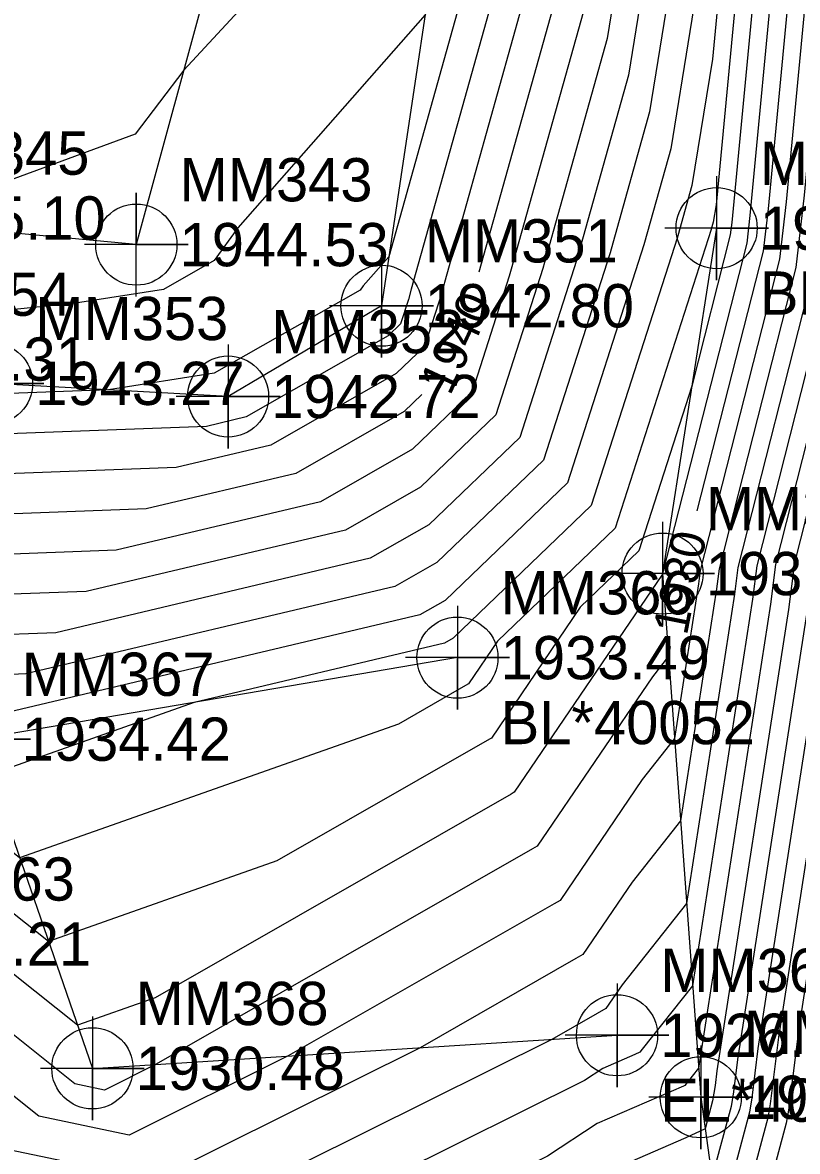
# Model space of a CAD drawing. Extents: x 1004378 to 1005103, y 553854 to 554288.
# Drawn here: x 1004921.7 to 1004966.5, y 553915.8 to 553981 of the extents above; entities that cross this region are included whole.
import ezdxf

# ---------------------------------------------------------------- set-up
doc = ezdxf.new("R2010")
doc.units = 0
for name, color, linetype in [('DTM Contours Major', 7, 'Continuous'), ('DTM Contours Major Text', 7, 'Continuous'), ('DTM Contours Minor', 7, 'Continuous'), ('Exist DTM Breakline', 7, 'Continuous'), ('Exist DTM Breakline Cogo Comment', 7, 'Continuous'), ('Exist DTM Breakline Cogo Elevation', 7, 'Continuous'), ('Exist DTM Breakline Cogo Number', 7, 'Continuous'), ('Exist DTM Breakline Cogo Point CELL', 7, 'Continuous'), ('Exist Roads Soil', 7, 'Continuous'), ('Exist Roads Soil Cogo Elevation', 7, 'Continuous'), ('Exist Roads Soil Cogo Number', 7, 'Continuous'), ('Exist Roads Soil Cogo Point CELL', 7, 'Continuous')]:
    doc.layers.add(name, color=color, linetype=linetype)

msp = doc.modelspace()

# ---------------------------------------------------------------- linework, layer by layer
at = {"layer": 'DTM Contours Major'}
for points in [[(1004952.659, 554065.091), (1004953.349, 554059.3), (1004954.06, 554055.889), (1004955.156, 554052.277), (1004953.842, 554048.264), (1004954.035, 554026.446), (1004955.827, 554009.057), (1004955.839, 554007.597), (1004955.608, 554000.346), (1004953.019, 553984.313), (1004948.054, 553966.564)], [(1004966.938, 554051.86), (1004967.829, 554048.921), (1004967.422, 554047.677), (1004967.482, 554040.91), (1004968.579, 554030.261), (1004968.073, 554007.661), (1004967.778, 554001.521), (1004967.551, 553999.619), (1004964.757, 553970.225), (1004964.471, 553967.778), (1004960.654, 553952.767)], [(1004947.118, 554041.088), (1004947.311, 554019.215), (1004947.454, 554017.827), (1004947.487, 554013.967), (1004946.931, 553996.538), (1004946.571, 553995.053), (1004931.009, 553978.241), (1004928.196, 553974.545), (1004916.189, 553970.124), (1004914.888, 553969.412), (1004912.358, 553969.149), (1004911.765, 553968.617), (1004911.067, 553969.318), (1004903.448, 553970.699)], [(1004962.31, 553997.555), (1004961.333, 553987.27), (1004959.141, 553973.696), (1004957.624, 553968.273), (1004957.585, 553968.134), (1004953.163, 553954.39), (1004946.098, 553947.597), (1004944.639, 553946.764), (1004920.141, 553940.962), (1004919.187, 553940.926), (1004918.652, 553940.867), (1004916.351, 553941.407), (1004903.524, 553943.188), (1004903.229, 553940.965)], [(1004971.479, 553987.875), (1004969.989, 553972.194), (1004969.198, 553965.438), (1004965.192, 553949.68), (1004964.904, 553947.376), (1004960.748, 553920.578), (1004960.368, 553920.099), (1004959.949, 553919.572), (1004959.874, 553919.536), (1004954.889, 553917.367), (1004952.025, 553915.484), (1004933.597, 553906.315), (1004932.685, 553906.503)], [(1004975.8, 553980.258), (1004975.22, 553974.163), (1004973.925, 553963.098), (1004970.627, 553950.123), (1004970.099, 553945.901), (1004966.549, 553923.013), (1004965.932, 553918.15), (1004965.808, 553917.384), (1004962.695, 553905.72), (1004954.669, 553902.046), (1004953.262, 553901.433), (1004941.713, 553893.841)], [(1004944.754, 553959.487), (1004943.743, 553958.515), (1004937.467, 553954.931), (1004928.829, 553952.886), (1004919.63, 553952.541), (1004914.473, 553951.967), (1004901.641, 553954.979), (1004896.468, 553952.368), (1004896.162, 553950.066), (1004894.709, 553945.812), (1004892.507, 553943.392)], [(1004959.1, 553944.929), (1004959.013, 553944.368), (1004958.077, 553943.19), (1004951.417, 553933.392), (1004951.155, 553933.242), (1004929.405, 553920.793), (1004926.414, 553919.305), (1004924.709, 553919.658), (1004920.162, 553923.286), (1004912.286, 553929.547), (1004910.029, 553929.86), (1004909.966, 553929.387), (1004909.292, 553927.413), (1004906.06, 553916.388), (1004903.403, 553900.976), (1004901.694, 553893.379)]]:
    msp.add_lwpolyline(points, dxfattribs=at)
at = {"layer": 'DTM Contours Minor'}
for points in [[(1004948.41, 554048.498), (1004948.656, 554020.661), (1004949.129, 554016.073), (1004949.157, 554012.693), (1004948.622, 553995.909), (1004948.121, 553992.807), (1004944.939, 553981.431), (1004934.117, 553969.131), (1004932.752, 553967.238), (1004929.819, 553965.57), (1004924.739, 553964.771), (1004916.73, 553963.94), (1004913.587, 553961.121), (1004911.131, 553960.847), (1004910.199, 553961.066), (1004909.391, 553960.658), (1004907.185, 553961.606), (1004903.082, 553965.731), (1004892.29, 553967.686), (1004891.326, 553967.931), (1004890.511, 553967.035)], [(1004949.768, 554048.44), (1004950.001, 554022.107), (1004950.803, 554014.319), (1004950.827, 554011.419), (1004950.368, 553997.019), (1004949.345, 553990.683), (1004942.849, 553967.456), (1004941.373, 553965.778), (1004941.187, 553965.52), (1004932.749, 553960.721), (1004926.659, 553959.763), (1004919.896, 553959.51), (1004911.966, 553958.627), (1004908.059, 553959.544), (1004904.674, 553957.836), (1004895.429, 553961.81), (1004895.097, 553962.143), (1004894.225, 553962.301), (1004892.484, 553962.744), (1004891.01, 553961.125)], [(1004951.126, 554048.381), (1004951.345, 554023.554), (1004952.478, 554012.565), (1004952.498, 554010.145), (1004952.115, 553998.128), (1004950.57, 553988.56), (1004944.141, 553965.574), (1004943.976, 553964.983), (1004943.524, 553963.577), (1004942.801, 553962.882), (1004934.598, 553958.198), (1004932.304, 553957.655), (1004919.808, 553957.187), (1004912.802, 553956.407), (1004905.92, 553958.023), (1004899.957, 553955.013), (1004894.62, 553957.307), (1004893.641, 553957.556), (1004891.509, 553955.214)], [(1004952.484, 554048.322), (1004952.69, 554025), (1004954.152, 554010.811), (1004954.168, 554008.871), (1004953.861, 553999.237), (1004951.794, 553986.437), (1004946.067, 553965.959), (1004945.92, 553965.433), (1004944.901, 553962.265), (1004943.272, 553960.699), (1004936.032, 553956.565), (1004930.566, 553955.27), (1004919.719, 553954.864), (1004913.638, 553954.187), (1004903.78, 553956.501), (1004895.24, 553952.191), (1004894.867, 553952.351), (1004894.798, 553952.369), (1004892.008, 553949.303)], [(1004955.2, 554048.205), (1004955.379, 554027.893), (1004957.501, 554007.303), (1004957.509, 554006.323), (1004957.354, 554001.455), (1004954.243, 553982.19), (1004949.919, 553966.731), (1004949.808, 553966.333), (1004947.655, 553959.64), (1004944.214, 553956.331), (1004938.901, 553953.298), (1004927.091, 553950.501), (1004919.542, 553950.218), (1004915.309, 553949.747), (1004899.502, 553953.458), (1004898.18, 553952.79), (1004897.542, 553947.998), (1004894.519, 553939.143), (1004893.007, 553937.482)], [(1004956.558, 554048.146), (1004956.724, 554029.339), (1004959.176, 554005.549), (1004959.18, 554005.049), (1004959.101, 554002.565), (1004955.467, 553980.066), (1004951.846, 553967.116), (1004951.753, 553966.783), (1004949.032, 553958.328), (1004944.685, 553954.148), (1004940.335, 553951.664), (1004925.354, 553948.116), (1004919.453, 553947.895), (1004916.145, 553947.527), (1004901.925, 553950.865), (1004899.622, 553951.185), (1004898.923, 553945.93), (1004894.328, 553932.475), (1004893.506, 553931.571)], [(1004957.916, 554048.088), (1004958.069, 554030.785), (1004960.85, 554003.795), (1004960.85, 554003.775), (1004960.847, 554003.674), (1004956.692, 553977.943), (1004953.772, 553967.502), (1004953.697, 553967.233), (1004950.409, 553957.015), (1004945.156, 553951.964), (1004941.77, 553950.031), (1004923.616, 553945.732), (1004919.364, 553945.572), (1004916.98, 553945.307), (1004906.734, 553947.712), (1004900.923, 553948.519), (1004900.303, 553943.862), (1004894.138, 553925.806), (1004894.005, 553925.66)], [(1004972.981, 554045.52), (1004972.185, 554009.926), (1004971.721, 554000.256), (1004971.362, 553997.261), (1004968.942, 553971.8), (1004968.253, 553965.906), (1004964.105, 553949.591), (1004963.865, 553947.671), (1004960.401, 553925.336), (1004957.491, 553921.673), (1004957.35, 553921.495), (1004957.063, 553921.358), (1004955.215, 553920.554), (1004954.153, 553919.855), (1004932.16, 553908.913), (1004916.353, 553912.182), (1004913.842, 553914.186), (1004913.087, 553911.609), (1004912.621, 553908.909), (1004907.637, 553886.746), (1004907.279, 553884.335), (1004906.612, 553883.292), (1004908.282, 553879.28)], [(1004975.015, 554045.638), (1004974.241, 554011.059), (1004973.692, 553999.624), (1004973.268, 553996.082), (1004971.035, 553972.588), (1004970.143, 553964.97), (1004966.279, 553949.768), (1004965.943, 553947.081), (1004961.807, 553920.414), (1004961.699, 553919.562), (1004961.557, 553918.68), (1004961.124, 553917.06), (1004960.01, 553916.55), (1004954.564, 553914.18), (1004949.897, 553911.112), (1004935.034, 553903.717), (1004920.298, 553906.764), (1004913.738, 553897.346), (1004910.842, 553884.469), (1004910.705, 553883.545), (1004910.449, 553883.146), (1004912.725, 553877.68)], [(1004976.003, 554044.458), (1004975.269, 554011.625), (1004974.678, 553999.308), (1004974.221, 553995.492), (1004972.081, 553972.981), (1004971.089, 553964.502), (1004967.366, 553949.857), (1004966.982, 553946.786), (1004962.993, 553921.064), (1004962.757, 553919.209), (1004962.62, 553918.356), (1004961.517, 553914.225), (1004958.675, 553912.924), (1004954.239, 553910.994), (1004947.768, 553906.74), (1004936.47, 553901.118), (1004925.269, 553903.435), (1004913.007, 553885.833), (1004912.444, 553883.33), (1004912.418, 553883.151), (1004912.368, 553883.073), (1004914.946, 553876.88)], [(1004976.992, 554043.278), (1004976.297, 554012.192), (1004975.663, 553998.992), (1004975.174, 553994.903), (1004973.128, 553973.375), (1004972.034, 553964.034), (1004968.453, 553949.946), (1004968.021, 553946.491), (1004964.178, 553921.714), (1004963.816, 553918.856), (1004963.683, 553918.032), (1004961.91, 553911.39), (1004957.339, 553909.298), (1004953.913, 553907.807), (1004945.64, 553902.368), (1004937.907, 553898.52), (1004930.24, 553900.106), (1004920.136, 553885.602), (1004914.696, 553882.016), (1004917.167, 553876.081)], [(1004977.981, 554042.098), (1004977.325, 554012.758), (1004976.649, 553998.676), (1004976.126, 553994.313), (1004974.174, 553973.769), (1004972.98, 553963.566), (1004969.54, 553950.035), (1004969.06, 553946.196), (1004965.364, 553922.363), (1004964.874, 553918.503), (1004964.745, 553917.708), (1004962.303, 553908.555), (1004956.004, 553905.672), (1004953.588, 553904.62), (1004943.512, 553897.997), (1004939.343, 553895.922), (1004935.21, 553896.777), (1004929.764, 553888.959), (1004917.155, 553880.646), (1004919.388, 553875.281)], [(1004971.881, 554041.705), (1004971.157, 554009.36), (1004970.735, 554000.573), (1004970.409, 553997.85), (1004967.896, 553971.406), (1004967.307, 553966.374), (1004963.018, 553949.502), (1004962.826, 553947.966), (1004960.054, 553930.094), (1004956.322, 553925.395), (1004955.382, 553924.012), (1004954.895, 553923.733), (1004952.275, 553922.234), (1004930.724, 553911.511), (1004918.442, 553914.051), (1004912.975, 553918.414), (1004911.33, 553912.804), (1004910.317, 553906.926), (1004906.034, 553887.884), (1004905.566, 553884.73), (1004904.694, 553883.365), (1004906.061, 553880.08)], [(1004966.137, 554039.463), (1004967.478, 554026.447), (1004967.045, 554007.095), (1004966.793, 554001.837), (1004966.598, 554000.209), (1004963.711, 553969.831), (1004963.525, 553968.246), (1004958.67, 553949.147), (1004958.67, 553949.145), (1004958.667, 553949.126), (1004958.663, 553949.121), (1004950.096, 553936.518), (1004949.909, 553936.411), (1004929.348, 553924.643), (1004924.856, 553923.056), (1004913.836, 553931.817), (1004908.728, 553932.526), (1004908.586, 553931.455), (1004907.061, 553926.988), (1004904.303, 553917.582), (1004901.098, 553898.992)], [(1004964.792, 554038.017), (1004966.378, 554022.632), (1004966.017, 554006.528), (1004965.807, 554002.153), (1004965.645, 554000.798), (1004962.665, 553969.437), (1004962.58, 553968.714), (1004960.36, 553959.981), (1004957.294, 553950.453), (1004953.909, 553947.198), (1004948.774, 553939.645), (1004948.663, 553939.581), (1004936.373, 553932.547), (1004923.184, 553927.887), (1004915.385, 553934.086), (1004907.427, 553935.191), (1004907.205, 553933.523), (1004904.829, 553926.563), (1004902.546, 553918.777), (1004898.793, 553897.009)], [(1004970.78, 554037.89), (1004970.129, 554008.794), (1004969.75, 554000.889), (1004969.456, 553998.44), (1004966.85, 553971.012), (1004966.362, 553966.842), (1004961.931, 553949.413), (1004961.787, 553948.261), (1004959.707, 553934.852), (1004956.907, 553931.326), (1004954.06, 553927.139), (1004953.648, 553926.903), (1004944.652, 553921.754), (1004929.287, 553914.109), (1004920.531, 553915.92), (1004912.107, 553922.642), (1004909.573, 553913.998), (1004908.012, 553904.943), (1004904.431, 553889.023), (1004903.852, 553885.125), (1004902.775, 553883.437), (1004903.84, 553880.88)], [(1004963.448, 554036.571), (1004965.277, 554018.817), (1004964.989, 554005.962), (1004964.822, 554002.47), (1004964.692, 554001.388), (1004961.753, 553970.463), (1004961.589, 553969.449), (1004961.476, 553969.044), (1004961.473, 553969.034), (1004955.917, 553951.766), (1004949.132, 553945.241), (1004947.453, 553942.771), (1004947.416, 553942.75), (1004943.398, 553940.451), (1004921.511, 553932.717), (1004916.934, 553936.356), (1004906.126, 553937.857), (1004905.825, 553935.591), (1004902.597, 553926.138), (1004900.789, 553919.972), (1004896.488, 553895.026)], [(1004962.103, 554035.124), (1004964.176, 554015.003), (1004963.961, 554005.396), (1004963.836, 554002.786), (1004963.739, 554001.977), (1004961.543, 553978.867), (1004960.365, 553971.573), (1004959.55, 553968.659), (1004959.529, 553968.584), (1004954.54, 553953.078), (1004946.569, 553945.413), (1004946.073, 553945.13), (1004931.594, 553941.701), (1004919.839, 553937.548), (1004918.483, 553938.626), (1004904.825, 553940.523), (1004904.444, 553937.659), (1004900.366, 553925.713), (1004899.032, 553921.166), (1004895.735, 553902.041), (1004895.123, 553902.853)], [(1004969.679, 554034.076), (1004969.101, 554008.227), (1004968.764, 554001.205), (1004968.504, 553999.029), (1004965.804, 553970.618), (1004965.416, 553967.31), (1004960.844, 553949.324), (1004960.748, 553948.556), (1004959.36, 553939.61), (1004957.492, 553937.258), (1004952.739, 553930.265), (1004952.402, 553930.072), (1004937.029, 553921.274), (1004927.851, 553916.707), (1004922.62, 553917.789), (1004911.24, 553926.87), (1004907.816, 553915.193), (1004905.707, 553902.959), (1004902.829, 553890.161), (1004902.139, 553885.52), (1004900.857, 553883.51), (1004901.619, 553881.68)], [(1004959.413, 554032.232), (1004961.975, 554007.374), (1004961.905, 554004.263), (1004961.865, 554003.418), (1004961.833, 554003.156), (1004961.122, 553995.674), (1004957.916, 553975.82), (1004955.698, 553967.888), (1004955.641, 553967.684), (1004951.786, 553955.703), (1004945.627, 553949.78), (1004943.204, 553948.397), (1004921.879, 553943.347), (1004919.275, 553943.249), (1004917.816, 553943.087), (1004911.542, 553944.56), (1004902.224, 553945.854), (1004901.684, 553941.794), (1004895.902, 553924.863), (1004895.519, 553923.556), (1004894.571, 553918.057), (1004894.395, 553918.29)]]:
    msp.add_lwpolyline(points, dxfattribs=at)
at = {"layer": 'Exist DTM Breakline'}
for points in [[(1004908.599, 554113.626), (1004928.542, 554104.358), (1004950.697, 554094.299), (1004945.541, 554080.331), (1004948.745, 554053.974), (1004946.395, 554048.586), (1004946.774, 554014.511), (1004946.946, 553994.845), (1004942.426, 553964.624), (1004933.56, 553959.38), (1004919.92, 553960.138), (1004910.869, 553961.543), (1004894.885, 553951.978), (1004894.101, 553924.52), (1004896.848, 553886.739), (1004896.026, 553883.694)], [(1004961.787, 553969.107), (1004958.665, 553949.147), (1004960.871, 553918.889), (1004964.5, 553892.691), (1004966.059, 553859.121)], [(1004946.811, 553944.29), (1004919.135, 553939.581), (1004925.719, 553920.561), (1004956.033, 553922.471)]]:
    msp.add_lwpolyline(points, dxfattribs=at)
at = {"layer": 'Exist DTM Breakline Cogo Point CELL'}
for points in [[(1004961.787, 553972.107), (1004961.787, 553966.107), (1004961.787, 553969.107), (1004964.787, 553969.107), (1004958.787, 553969.107)], [(1004942.426, 553967.624), (1004942.426, 553961.624), (1004942.426, 553964.624), (1004945.426, 553964.624), (1004939.426, 553964.624)], [(1004919.92, 553963.138), (1004919.92, 553957.138), (1004919.92, 553960.138), (1004922.92, 553960.138), (1004916.92, 553960.138)], [(1004933.56, 553962.38), (1004933.56, 553956.38), (1004933.56, 553959.38), (1004936.56, 553959.38), (1004930.56, 553959.38)], [(1004958.665, 553952.147), (1004958.665, 553946.147), (1004958.665, 553949.147), (1004961.665, 553949.147), (1004955.665, 553949.147)], [(1004946.811, 553947.29), (1004946.811, 553941.29), (1004946.811, 553944.29), (1004949.811, 553944.29), (1004943.811, 553944.29)], [(1004919.135, 553942.581), (1004919.135, 553936.581), (1004919.135, 553939.581), (1004922.135, 553939.581), (1004916.135, 553939.581)], [(1004956.033, 553925.471), (1004956.033, 553919.471), (1004956.033, 553922.471), (1004959.033, 553922.471), (1004953.033, 553922.471)], [(1004925.719, 553923.561), (1004925.719, 553917.561), (1004925.719, 553920.561), (1004928.719, 553920.561), (1004922.719, 553920.561)], [(1004960.871, 553921.889), (1004960.871, 553915.889), (1004960.871, 553918.889), (1004963.871, 553918.889), (1004957.871, 553918.889)]]:
    msp.add_lwpolyline(points, dxfattribs=at)
for centre in [(1004961.787, 553969.107), (1004942.426, 553964.624), (1004919.92, 553960.138), (1004933.56, 553959.38), (1004958.665, 553949.147), (1004946.811, 553944.29), (1004956.033, 553922.471), (1004925.719, 553920.561), (1004960.871, 553918.889)]:
    msp.add_circle(centre, 2.344, dxfattribs=at)
at = {"layer": 'Exist Roads Soil'}
msp.add_lwpolyline([(1004902.345, 554049.201), (1004911.013, 554044.44), (1004908.227, 554025.602), (1004914.669, 554009.493), (1004937.036, 554000.34), (1004928.257, 553968.154), (1004911.901, 553969.693), (1004894.395, 553961.828)], dxfattribs=at)
at = {"layer": 'Exist Roads Soil Cogo Point CELL'}
msp.add_lwpolyline([(1004928.257, 553965.154), (1004928.257, 553971.154), (1004928.257, 553968.154), (1004931.257, 553968.154), (1004925.257, 553968.154)], dxfattribs=at)
msp.add_circle((1004928.257, 553968.154), 2.344, dxfattribs=at)

# ---------------------------------------------------------------- texts
at = {"layer": 'DTM Contours Major Text'}
for s, rotation, p in [('1940', 64.99541, (1004946.387, 553959.378)), ('1930', 78.78558, (1004960.067, 553945.528))]:
    msp.add_text(s, height=2, rotation=rotation, dxfattribs=at).set_placement(p)
at = {"layer": 'Exist DTM Breakline Cogo Comment'}
for s, p in [('BL*40052', (1004964.287, 553964.107)), ('BL*40052', (1004949.311, 553939.29)), ('EL*40052', (1004958.533, 553917.471))]:
    msp.add_text(s, height=2.5, dxfattribs=at).set_placement(p)
at = {"layer": 'Exist DTM Breakline Cogo Elevation'}
for s, p in [('1932.84', (1004964.287, 553967.857)), ('1942.80', (1004944.926, 553963.374)), ('1944.31', (1004913.369, 553960.293)), ('1943.27', (1004922.42, 553958.888)), ('1942.72', (1004936.06, 553958.13)), ('1931.00', (1004961.165, 553947.897)), ('1933.49', (1004949.311, 553943.04)), ('1934.42', (1004921.635, 553938.331)), ('1929.21', (1004913.56, 553926.5)), ('1926.51', (1004958.533, 553921.221)), ('1930.48', (1004928.219, 553919.311)), ('1924.65', (1004963.371, 553917.639))]:
    msp.add_text(s, height=2.5, dxfattribs=at).set_placement(p)
at = {"layer": 'Exist DTM Breakline Cogo Number'}
for s, p in [('MM370', (1004964.287, 553971.607)), ('MM351', (1004944.926, 553967.124)), ('MM354', (1004913.369, 553964.043)), ('MM353', (1004922.42, 553962.638)), ('MM352', (1004936.06, 553961.88)), ('MM371', (1004961.165, 553951.647)), ('MM366', (1004949.311, 553946.79)), ('MM367', (1004921.635, 553942.081)), ('MM363', (1004913.56, 553930.25)), ('MM369', (1004958.533, 553924.971)), ('MM368', (1004928.219, 553923.061)), ('MM372', (1004963.371, 553921.389))]:
    msp.add_text(s, height=2.5, dxfattribs=at).set_placement(p)
at = {"layer": 'Exist Roads Soil Cogo Elevation'}
for s, p in [('1945.10', (1004914.401, 553968.443)), ('1944.53', (1004930.757, 553966.904))]:
    msp.add_text(s, height=2.5, dxfattribs=at).set_placement(p)
at = {"layer": 'Exist Roads Soil Cogo Number'}
for s, p in [('MM345', (1004914.401, 553972.193)), ('MM343', (1004930.757, 553970.654))]:
    msp.add_text(s, height=2.5, dxfattribs=at).set_placement(p)

doc.saveas('drawing.dxf')
